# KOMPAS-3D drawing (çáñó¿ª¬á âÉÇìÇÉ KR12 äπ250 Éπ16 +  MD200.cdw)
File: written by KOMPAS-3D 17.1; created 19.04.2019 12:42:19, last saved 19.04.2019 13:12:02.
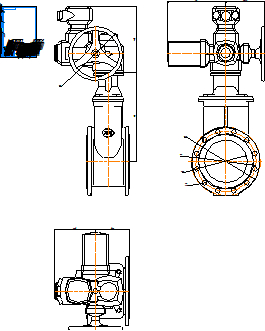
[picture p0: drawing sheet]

Sheet 1: A4, portrait

Title block, sheet 1: name: Задвижка ГРАНАР KR12 Ду250 Ру16 + / MD200; material: Внимание! Данный продукт является объектом авторского права ООО «Торговый Дом АДЛ». / Запрещается изменение, копирование, распространение / (в том числе путем копирования на другие сайты и ресурсы в Интернете) / или любое иное использование информации и объектов без предварительного / согласия правообладателя (ООО «Торговый Дом АДЛ»).; mass: 303,42; sheets: 1; organisation: ООО "Торговый дом АДЛ"; sheet format: A4; stored path: \\adlc.lan\data\АДЛ_ПКД\3D-модели\ADL production\Клиновые задвижки серии KR ГРАНАР\Клиновые задвижки KR12 с эл.приводами Смартгир\KOMPAS 2D\Задвижка ГРАНАР KR12 Ду250 Ру16 +  MD200.cdw

Views: Вид 1, Проекционный вид 3
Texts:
  user
Dimensions and other numbers on the sheet: 405; 355; 521; 391; 320; 241,19; 198,81; 1:1; 1; 303,42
